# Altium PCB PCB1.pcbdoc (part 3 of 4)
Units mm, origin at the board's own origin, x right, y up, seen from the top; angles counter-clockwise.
Board outline 77.9 x 107.7 mm, 4 copper layers (Top Layer, Inner1, Inner2, Bottom Layer); 106 components, 123 nets, 650 pads, 272 vias.
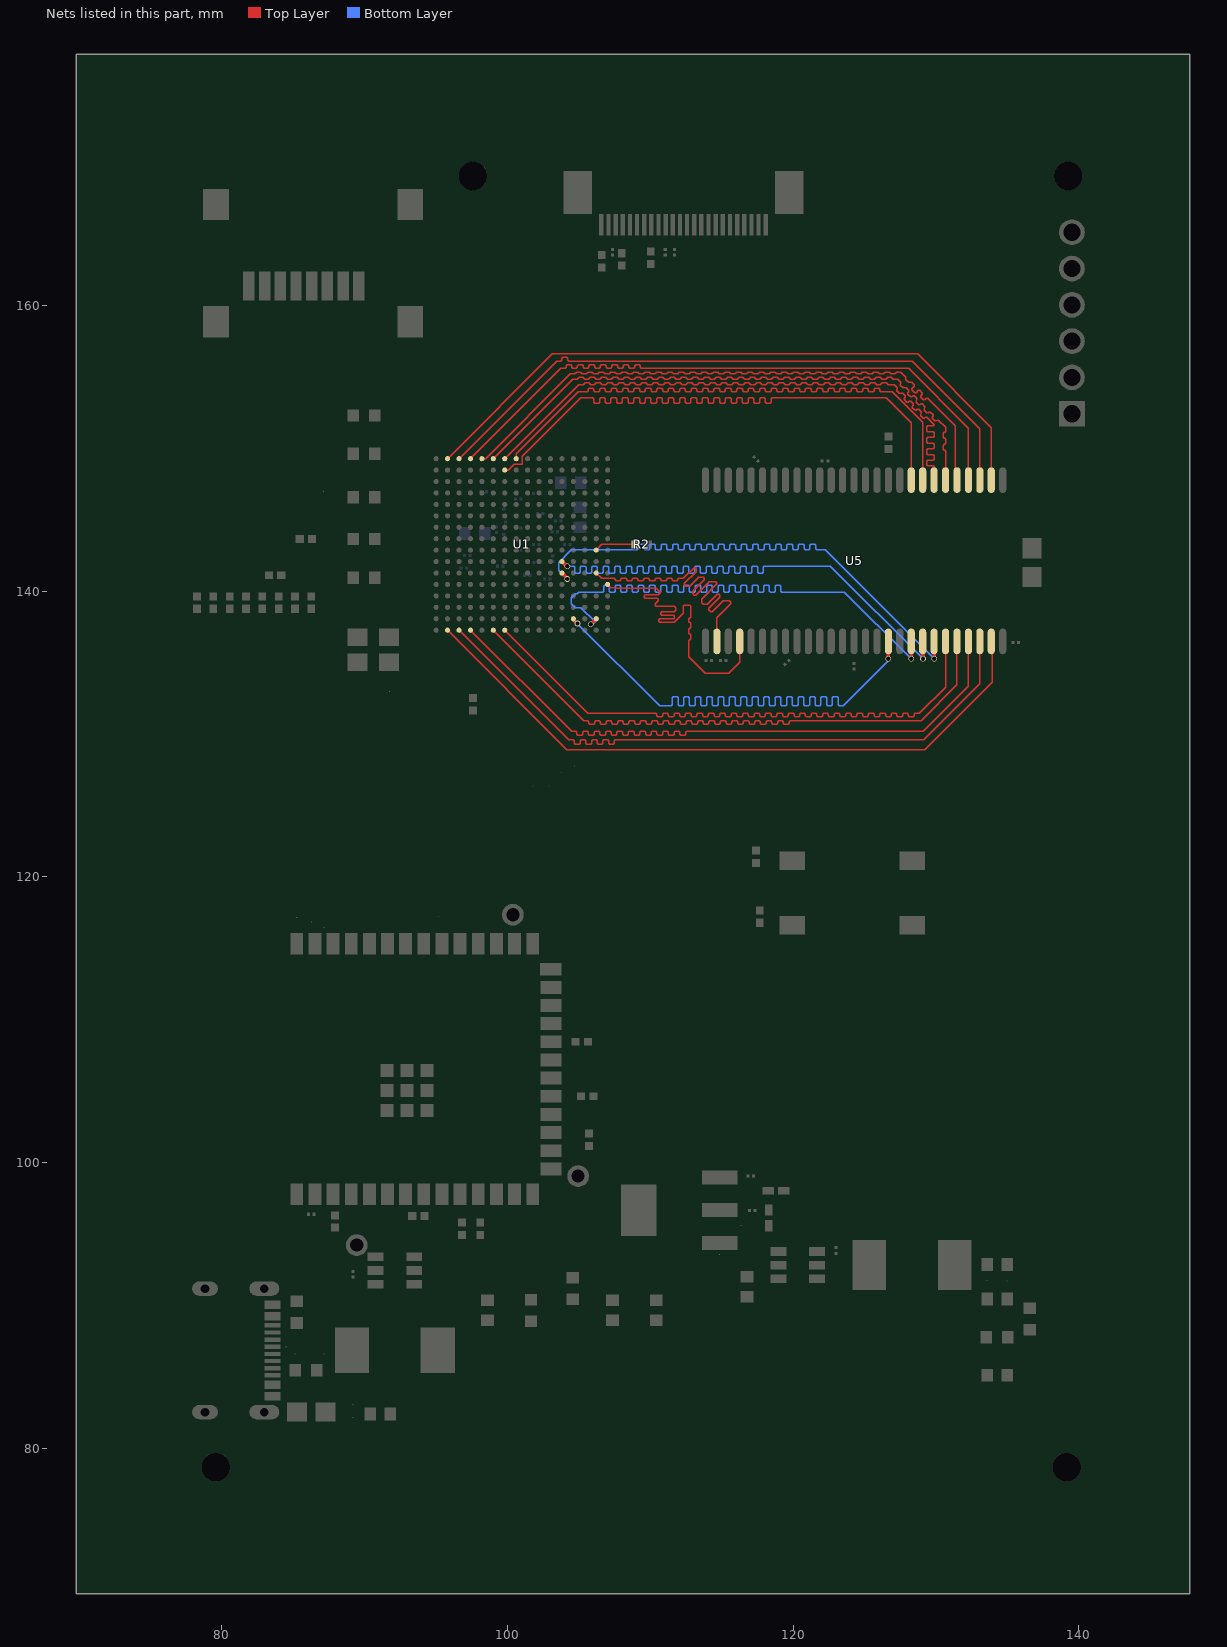
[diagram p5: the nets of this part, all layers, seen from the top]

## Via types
v1: diameter 0.4, hole 0.3, Top Layer to Bottom Layer, 269 vias
v2: diameter 0.5, hole 0.3, Top Layer to Bottom Layer, 3 vias

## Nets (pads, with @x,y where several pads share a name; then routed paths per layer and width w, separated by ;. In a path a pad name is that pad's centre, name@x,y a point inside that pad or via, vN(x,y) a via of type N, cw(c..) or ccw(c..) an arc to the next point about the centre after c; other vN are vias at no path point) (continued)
SD_A0: U1.T6 U5.23 | length 45.3
  Top Layer w0.1: U1.T6@99.024,137.26 105.343,130.941 105.643,130.941 105.714,130.87 105.714,130.758 105.784,130.687 106.043,130.687 106.114,130.758 106.114,130.87 106.184,130.941 106.443,130.941 106.514,130.87 106.514,130.758 106.584,130.687 106.843,130.687 106.914,130.758 106.914,130.87 106.984,130.941 107.243,130.941 107.314,130.87 107.314,130.758 107.384,130.687 107.643,130.687 107.714,130.758 107.714,130.87 107.784,130.941 108.043,130.941 108.114,130.87 108.114,130.758 108.184,130.687 108.443,130.687 108.514,130.758 108.514,130.87 108.584,130.941 108.843,130.941 108.914,130.87 108.914,130.758 108.984,130.687 109.243,130.687 109.314,130.758 109.314,130.87 109.384,130.941 109.643,130.941 109.714,130.87 109.714,130.758 109.784,130.687 110.043,130.687 110.114,130.758 110.114,130.87 110.184,130.941 110.443,130.941 110.514,130.87 110.514,130.758 110.584,130.687 110.843,130.687 110.914,130.758 110.914,130.87 110.984,130.941 111.243,130.941 111.314,130.87 111.314,130.758 111.384,130.687 111.643,130.687 111.714,130.758 111.714,130.87 111.784,130.941 112.043,130.941 112.114,130.87 112.114,130.758 112.184,130.687 112.443,130.687 112.514,130.758 112.514,130.87 112.584,130.941 112.843,130.941 112.914,130.87 112.914,130.758 112.984,130.687 113.243,130.687 113.314,130.758 113.314,130.87 113.384,130.941 113.643,130.941 113.714,130.87 113.714,130.758 113.784,130.687 114.043,130.687 114.114,130.758 114.114,130.87 114.184,130.941 114.443,130.941 114.514,130.87 114.514,130.758 114.584,130.687 114.843,130.687 114.914,130.758 114.914,130.87 114.984,130.941 115.243,130.941 115.314,130.87 115.314,130.758 115.384,130.687 115.643,130.687 115.714,130.758 115.714,130.87 115.784,130.941 116.043,130.941 116.114,130.87 116.114,130.758 116.184,130.687 116.443,130.687 116.514,130.758 116.514,130.87 116.584,130.941 116.843,130.941 116.914,130.87 116.914,130.758 116.984,130.687 117.243,130.687 117.314,130.758 117.314,130.87 117.384,130.941 117.643,130.941 117.714,130.87 117.714,130.758 117.784,130.687 118.043,130.687 118.114,130.758 118.114,130.87 118.184,130.941 118.443,130.941 118.514,130.87 118.514,130.758 118.584,130.687 118.843,130.687 118.914,130.758 118.914,130.87 118.984,130.941 119.243,130.941 119.314,130.87 119.314,130.758 119.384,130.687 119.643,130.687 119.714,130.758 119.714,130.87 119.784,130.941 128.964,130.941 131.465,133.442 U5.23@131.465,136.475
SD_A1: U1.T4 U5.24 | length 45.6
  Top Layer w0.1: U1.T4@97.424,137.26 104.505,130.179 104.805,130.179 104.876,130.108 104.876,129.996 104.946,129.925 105.205,129.925 105.276,129.996 105.276,130.108 105.346,130.179 105.605,130.179 105.676,130.108 105.676,129.996 105.746,129.925 106.005,129.925 106.076,129.996 106.076,130.108 106.146,130.179 106.405,130.179 106.476,130.108 106.476,129.996 106.546,129.925 106.805,129.925 106.876,129.996 106.876,130.108 106.946,130.179 107.205,130.179 107.276,130.108 107.276,129.996 107.346,129.925 107.605,129.925 107.676,129.996 107.676,130.108 107.746,130.179 108.005,130.179 108.076,130.108 108.076,129.996 108.146,129.925 108.405,129.925 108.476,129.996 108.476,130.108 108.546,130.179 108.805,130.179 108.876,130.108 108.876,129.996 108.946,129.925 109.205,129.925 109.276,129.996 109.276,130.108 109.346,130.179 109.605,130.179 109.676,130.108 109.676,129.996 109.746,129.925 110.005,129.925 110.076,129.996 110.076,130.108 110.146,130.179 110.405,130.179 110.476,130.108 110.476,129.996 110.546,129.925 110.805,129.925 110.876,129.996 110.876,130.108 110.946,130.179 111.205,130.179 111.276,130.108 111.276,129.996 111.346,129.925 111.605,129.925 111.676,129.996 111.676,130.108 111.746,130.179 112.005,130.179 112.076,130.108 112.076,129.996 112.146,129.925 112.405,129.925 112.476,129.996 112.476,130.108 112.546,130.179 129.091,130.179 132.266,133.354 U5.24@132.265,136.475
SD_A2: U1.T3 U5.25 | length 45.9
  Top Layer w0.1: U1.T3@96.624,137.26 104.303,129.581 104.626,129.581 104.697,129.51 104.697,129.361 104.767,129.29 105.026,129.29 105.097,129.361 105.097,129.51 105.167,129.581 105.426,129.581 105.497,129.51 105.497,129.361 105.567,129.29 105.826,129.29 105.897,129.361 105.897,129.51 105.967,129.581 106.226,129.581 106.297,129.51 106.297,129.361 106.367,129.29 106.626,129.29 106.697,129.361 106.697,129.51 106.767,129.581 107.026,129.581 107.097,129.51 107.097,129.361 107.167,129.29 107.426,129.29 107.497,129.361 107.497,129.51 107.567,129.581 129.128,129.581 133.065,133.518 U5.25@133.065,136.475
SD_A3: U1.T2 U5.26 | length 46.4
  Top Layer w0.1: U1.T2@95.824,137.26 104.175,128.909 129.218,128.909 133.917,133.608 133.917,136.423 U5.26@133.865,136.475
SD_A4: U1.A2 U5.29 | length 46.9
  Top Layer w0.1: U1.A2@95.824,149.26 103.159,156.595 128.71,156.595 133.865,151.44 U5.29@133.865,147.759
SD_A5: U1.A3 U5.30 | length 45.2
  Top Layer w0.1: U1.A3@96.624,149.26 103.451,156.087 103.751,156.087 103.821,156.158 103.821,156.27 103.892,156.341 104.151,156.341 104.221,156.27 104.221,156.158 104.292,156.087 128.329,156.087 133.065,151.351 U5.30@133.065,147.759
SD_A6: U1.A4 U5.31 | length 45.2
  Top Layer w0.1: U1.A4@97.424,149.26 103.743,155.579 104.043,155.579 104.114,155.65 104.114,155.762 104.184,155.833 104.443,155.833 104.514,155.762 104.514,155.65 104.584,155.579 104.843,155.579 104.914,155.65 104.914,155.762 104.984,155.833 105.243,155.833 105.314,155.762 105.314,155.65 105.384,155.579 105.643,155.579 105.714,155.65 105.714,155.762 105.784,155.833 106.043,155.833 106.114,155.762 106.114,155.65 106.184,155.579 106.443,155.579 106.514,155.65 106.514,155.762 106.584,155.833 106.843,155.833 106.914,155.762 106.914,155.65 106.984,155.579 107.243,155.579 107.314,155.65 107.314,155.762 107.384,155.833 107.643,155.833 107.714,155.762 107.714,155.65 107.784,155.579 108.043,155.579 108.114,155.65 108.114,155.762 108.184,155.833 108.443,155.833 108.514,155.762 108.514,155.65 108.584,155.579 108.843,155.579 108.914,155.65 108.914,155.762 108.984,155.833 109.243,155.833 109.314,155.762 109.314,155.65 109.384,155.579 128.075,155.579 132.265,151.389 U5.31@132.265,147.759
SD_A7: U1.A5 U5.32 | length 45.1
  Top Layer w0.1: U1.A5@98.224,149.26 98.484,149.26 104.422,155.198 104.722,155.198 104.849,155.325 105.122,155.325 105.249,155.198 105.522,155.198 105.649,155.325 105.922,155.325 106.049,155.198 106.322,155.198 106.449,155.325 106.722,155.325 106.849,155.198 107.122,155.198 107.249,155.325 107.522,155.325 107.649,155.198 107.922,155.198 108.049,155.325 108.322,155.325 108.449,155.198 108.722,155.198 108.849,155.325 109.122,155.325 109.249,155.198 109.522,155.198 109.649,155.325 109.922,155.325 110.049,155.198 110.322,155.198 110.449,155.325 110.722,155.325 110.849,155.198 111.122,155.198 111.249,155.325 111.522,155.325 111.649,155.198 111.922,155.198 112.049,155.325 112.322,155.325 112.449,155.198 112.722,155.198 112.849,155.325 113.122,155.325 113.249,155.198 113.522,155.198 113.649,155.325 113.922,155.325 114.049,155.198 114.322,155.198 114.449,155.325 114.722,155.325 114.849,155.198 115.122,155.198 115.249,155.325 115.522,155.325 115.649,155.198 115.922,155.198 116.049,155.325 116.322,155.325 116.449,155.198 116.722,155.198 116.849,155.325 117.122,155.325 117.249,155.198 117.522,155.198 117.649,155.325 117.922,155.325 118.049,155.198 118.322,155.198 118.449,155.325 118.722,155.325 118.849,155.198 119.122,155.198 119.249,155.325 119.522,155.325 119.649,155.198 119.922,155.198 120.049,155.325 120.322,155.325 120.449,155.198 120.722,155.198 120.849,155.325 121.122,155.325 121.249,155.198 121.522,155.198 121.649,155.325 121.922,155.325 122.049,155.198 122.322,155.198 122.449,155.325 122.722,155.325 122.849,155.198 123.122,155.198 123.249,155.325 123.522,155.325 123.649,155.198 123.922,155.198 124.049,155.325 124.322,155.325 124.449,155.198 124.722,155.198 124.849,155.325 125.122,155.325 125.249,155.198 125.522,155.198 125.649,155.325 125.922,155.325 126.049,155.198 126.322,155.198 126.449,155.325 126.722,155.325 126.849,155.198 127.122,155.198 127.249,155.325 127.522,155.325 127.894,154.953 127.894,154.774 128.077,154.591 128.177,154.591 128.189,154.603 128.289,154.603 128.472,154.42 128.472,154.32 128.317,154.166 128.317,154.066 128.5,153.883 128.6,153.883 128.754,154.037 128.854,154.037 129.037,153.854 129.037,153.754 128.932,153.649 128.932,153.549 129.114,153.366 129.214,153.366 129.32,153.472 129.42,153.472 131.338,151.554 131.338,147.886 U5.32@131.465,147.759
SD_A8: U1.A6 U5.33 | length 44.4
  Top Layer w0.1: U1.A6@99.024,149.26 104.581,154.817 104.881,154.817 104.952,154.888 104.952,154.898 105.022,154.969 105.281,154.969 105.352,154.898 105.352,154.888 105.422,154.817 105.681,154.817 105.752,154.888 105.752,154.898 105.822,154.969 106.081,154.969 106.152,154.898 106.152,154.888 106.222,154.817 106.481,154.817 106.552,154.888 106.552,154.898 106.622,154.969 106.881,154.969 106.952,154.898 106.952,154.888 107.022,154.817 107.281,154.817 107.352,154.888 107.352,154.898 107.422,154.969 107.681,154.969 107.752,154.898 107.752,154.888 107.822,154.817 108.081,154.817 108.152,154.888 108.152,154.898 108.222,154.969 108.481,154.969 108.552,154.898 108.552,154.888 108.622,154.817 108.881,154.817 108.952,154.888 108.952,154.898 109.022,154.969 109.281,154.969 109.352,154.898 109.352,154.888 109.422,154.817 109.681,154.817 109.752,154.888 109.752,154.898 109.822,154.969 110.081,154.969 110.152,154.898 110.152,154.888 110.222,154.817 110.481,154.817 110.552,154.888 110.552,154.898 110.622,154.969 110.881,154.969 110.952,154.898 110.952,154.888 111.022,154.817 111.281,154.817 111.352,154.888 111.352,154.898 111.422,154.969 111.681,154.969 111.752,154.898 111.752,154.888 111.822,154.817 112.081,154.817 112.152,154.888 112.152,154.898 112.222,154.969 112.481,154.969 112.552,154.898 112.552,154.888 112.622,154.817 112.881,154.817 112.952,154.888 112.952,154.898 113.022,154.969 113.281,154.969 113.352,154.898 113.352,154.888 113.422,154.817 113.681,154.817 113.752,154.888 113.752,154.898 113.822,154.969 114.081,154.969 114.152,154.898 114.152,154.888 114.222,154.817 114.481,154.817 114.552,154.888 114.552,154.898 114.622,154.969 114.881,154.969 114.952,154.898 114.952,154.888 115.022,154.817 115.281,154.817 115.352,154.888 115.352,154.898 115.422,154.969 115.681,154.969 115.752,154.898 115.752,154.888 115.822,154.817 116.081,154.817 116.152,154.888 116.152,154.898 116.222,154.969 116.481,154.969 116.552,154.898 116.552,154.888 116.622,154.817 116.881,154.817 116.952,154.888 116.952,154.898 117.022,154.969 117.281,154.969 117.352,154.898 117.352,154.888 117.422,154.817 117.681,154.817 117.752,154.888 117.752,154.898 117.822,154.969 118.081,154.969 118.152,154.898 118.152,154.888 118.222,154.817 118.481,154.817 118.552,154.888 118.552,154.898 118.622,154.969 118.881,154.969 118.952,154.898 118.952,154.888 119.022,154.817 119.281,154.817 119.352,154.888 119.352,154.898 119.422,154.969 119.681,154.969 119.752,154.898 119.752,154.888 119.822,154.817 120.081,154.817 120.152,154.888 120.152,154.898 120.222,154.969 120.481,154.969 120.552,154.898 120.552,154.888 120.622,154.817 120.881,154.817 120.952,154.888 120.952,154.898 121.022,154.969 121.281,154.969 121.352,154.898 121.352,154.888 121.422,154.817 121.681,154.817 121.752,154.888 121.752,154.898 121.822,154.969 122.081,154.969 122.152,154.898 122.152,154.888 122.222,154.817 122.481,154.817 122.552,154.888 122.552,154.898 122.622,154.969 122.881,154.969 122.952,154.898 122.952,154.888 123.022,154.817 123.281,154.817 123.352,154.888 123.352,154.898 123.422,154.969 123.681,154.969 123.752,154.898 123.752,154.888 123.822,154.817 124.081,154.817 124.152,154.888 124.152,154.898 124.222,154.969 124.481,154.969 124.552,154.898 124.552,154.888 124.622,154.817 124.881,154.817 124.952,154.888 124.952,154.898 125.022,154.969 125.281,154.969 125.352,154.898 125.352,154.888 125.422,154.817 125.681,154.817 125.752,154.888 125.752,154.898 125.822,154.969 126.081,154.969 126.152,154.898 126.152,154.888 126.222,154.817 126.481,154.817 126.552,154.888 126.552,154.898 126.622,154.969 126.881,154.969 126.952,154.898 126.952,154.888 127.022,154.817 127.313,154.817 127.525,154.605 127.525,154.505 127.513,154.493 127.513,154.393 127.696,154.21 127.796,154.21 127.808,154.222 127.908,154.222 128.091,154.039 128.091,153.939 128.035,153.884 128.035,153.784 128.218,153.601 128.318,153.601 128.373,153.656 128.473,153.656 128.656,153.473 128.656,153.373 128.601,153.318 128.601,153.218 128.784,153.035 128.884,153.035 128.939,153.091 129.039,153.091 129.222,152.908 129.222,152.808 129.167,152.752 129.167,152.652 129.349,152.47 129.449,152.47 129.505,152.525 129.605,152.525 129.788,152.342 129.788,152.242 129.741,152.196 129.741,152.096 129.924,151.913 130.024,151.913 130.071,151.959 130.171,151.959 130.665,151.465 130.665,151.165 130.594,151.094 130.577,151.094 130.506,151.024 130.506,150.765 130.577,150.694 130.594,150.694 130.665,150.624 130.665,150.324 130.594,150.253 130.577,150.253 130.506,150.182 130.506,149.924 130.577,149.853 130.594,149.853 130.665,149.782 U5.33@130.665,147.759
SD_A9: U1.A7 U5.34 | length 45.4
  Top Layer w0.1: U1.A7@99.824,149.26 105,154.436 105.3,154.436 105.371,154.507 105.371,154.517 105.441,154.588 105.7,154.588 105.771,154.517 105.771,154.507 105.841,154.436 106.1,154.436 106.171,154.507 106.171,154.517 106.241,154.588 106.5,154.588 106.571,154.517 106.571,154.507 106.641,154.436 106.9,154.436 106.971,154.507 106.971,154.517 107.041,154.588 107.3,154.588 107.371,154.517 107.371,154.507 107.441,154.436 107.7,154.436 107.771,154.507 107.771,154.517 107.841,154.588 108.1,154.588 108.171,154.517 108.171,154.507 108.241,154.436 108.5,154.436 108.571,154.507 108.571,154.517 108.641,154.588 108.9,154.588 108.971,154.517 108.971,154.507 109.041,154.436 109.3,154.436 109.371,154.507 109.371,154.517 109.441,154.588 109.7,154.588 109.771,154.517 109.771,154.507 109.841,154.436 110.1,154.436 110.171,154.507 110.171,154.517 110.241,154.588 110.5,154.588 110.571,154.517 110.571,154.507 110.641,154.436 110.9,154.436 110.971,154.507 110.971,154.517 111.041,154.588 111.3,154.588 111.371,154.517 111.371,154.507 111.441,154.436 111.7,154.436 111.771,154.507 111.771,154.517 111.841,154.588 112.1,154.588 112.171,154.517 112.171,154.507 112.241,154.436 112.5,154.436 112.571,154.507 112.571,154.517 112.641,154.588 112.9,154.588 112.971,154.517 112.971,154.507 113.041,154.436 113.3,154.436 113.371,154.507 113.371,154.517 113.441,154.588 113.7,154.588 113.771,154.517 113.771,154.507 113.841,154.436 114.1,154.436 114.171,154.507 114.171,154.517 114.241,154.588 114.5,154.588 114.571,154.517 114.571,154.507 114.641,154.436 114.9,154.436 114.971,154.507 114.971,154.517 115.041,154.588 115.3,154.588 115.371,154.517 115.371,154.507 115.441,154.436 115.7,154.436 115.771,154.507 115.771,154.517 115.841,154.588 116.1,154.588 116.171,154.517 116.171,154.507 116.241,154.436 116.5,154.436 116.571,154.507 116.571,154.517 116.641,154.588 116.9,154.588 116.971,154.517 116.971,154.507 117.041,154.436 117.3,154.436 117.371,154.507 117.371,154.517 117.441,154.588 117.7,154.588 117.771,154.517 117.771,154.507 117.841,154.436 118.1,154.436 118.171,154.507 118.171,154.517 118.241,154.588 118.5,154.588 118.571,154.517 118.571,154.507 118.641,154.436 118.9,154.436 118.971,154.507 118.971,154.517 119.041,154.588 119.3,154.588 119.371,154.517 119.371,154.507 119.441,154.436 119.7,154.436 119.771,154.507 119.771,154.517 119.841,154.588 120.1,154.588 120.171,154.517 120.171,154.507 120.241,154.436 120.5,154.436 120.571,154.507 120.571,154.517 120.641,154.588 120.9,154.588 120.971,154.517 120.971,154.507 121.041,154.436 121.3,154.436 121.371,154.507 121.371,154.517 121.441,154.588 121.7,154.588 121.771,154.517 121.771,154.507 121.841,154.436 122.1,154.436 122.171,154.507 122.171,154.517 122.241,154.588 122.5,154.588 122.571,154.517 122.571,154.507 122.641,154.436 122.9,154.436 122.971,154.507 122.971,154.517 123.041,154.588 123.3,154.588 123.371,154.517 123.371,154.507 123.441,154.436 123.7,154.436 123.771,154.507 123.771,154.517 123.841,154.588 124.1,154.588 124.171,154.517 124.171,154.507 124.241,154.436 124.5,154.436 124.571,154.507 124.571,154.517 124.641,154.588 124.9,154.588 124.971,154.517 124.971,154.507 125.041,154.436 125.3,154.436 125.371,154.507 125.371,154.517 125.441,154.588 125.7,154.588 125.771,154.517 125.771,154.507 125.841,154.436 126.1,154.436 126.171,154.507 126.171,154.517 126.241,154.588 126.5,154.588 126.571,154.517 126.571,154.507 126.641,154.436 127.059,154.436 127.271,154.224 127.271,154.124 127.259,154.112 127.259,154.012 127.442,153.829 127.542,153.829 127.554,153.841 127.654,153.841 127.837,153.658 127.837,153.558 127.781,153.503 127.781,153.403 127.964,153.22 128.064,153.22 128.119,153.275 128.219,153.275 128.402,153.092 128.402,152.992 128.347,152.937 128.347,152.837 128.53,152.654 128.63,152.654 128.685,152.71 128.785,152.71 128.968,152.527 128.968,152.427 128.913,152.371 128.913,152.271 129.095,152.089 129.195,152.089 129.251,152.144 129.351,152.144 129.865,151.63 129.865,151.622 129.794,151.551 129.416,151.551 129.345,151.481 129.345,151.222 129.416,151.151 129.794,151.151 129.865,151.081 129.865,150.822 129.794,150.751 129.416,150.751 129.345,150.681 129.345,150.422 129.416,150.351 129.794,150.351 129.865,150.281 129.865,150.022 129.794,149.951 129.416,149.951 129.345,149.881 129.345,149.622 129.416,149.551 129.794,149.551 129.865,149.481 129.865,149.222 129.794,149.151 129.416,149.151 129.345,149.081 129.345,148.822 129.416,148.751 129.794,148.751 129.865,148.681 U5.34@129.865,147.759
SD_A10: U1.T7 U5.22 | length 45.1
  Top Layer w0.1: U1.T7@99.824,137.26 105.635,131.449 110.395,131.449 110.466,131.378 110.466,131.266 110.537,131.195 110.795,131.195 110.866,131.266 110.866,131.378 110.937,131.449 111.195,131.449 111.266,131.378 111.266,131.266 111.337,131.195 111.595,131.195 111.666,131.266 111.666,131.378 111.737,131.449 111.995,131.449 112.066,131.378 112.066,131.266 112.137,131.195 112.395,131.195 112.466,131.266 112.466,131.378 112.537,131.449 112.795,131.449 112.866,131.378 112.866,131.266 112.937,131.195 113.195,131.195 113.266,131.266 113.266,131.378 113.337,131.449 113.595,131.449 113.666,131.378 113.666,131.266 113.737,131.195 113.995,131.195 114.066,131.266 114.066,131.378 114.137,131.449 114.395,131.449 114.466,131.378 114.466,131.266 114.537,131.195 114.795,131.195 114.866,131.266 114.866,131.378 114.937,131.449 115.195,131.449 115.266,131.378 115.266,131.266 115.337,131.195 115.595,131.195 115.666,131.266 115.666,131.378 115.737,131.449 115.995,131.449 116.066,131.378 116.066,131.266 116.137,131.195 116.395,131.195 116.466,131.266 116.466,131.378 116.537,131.449 116.795,131.449 116.866,131.378 116.866,131.266 116.937,131.195 117.195,131.195 117.266,131.266 117.266,131.378 117.337,131.449 117.595,131.449 117.666,131.378 117.666,131.266 117.737,131.195 117.995,131.195 118.066,131.266 118.066,131.378 118.137,131.449 118.395,131.449 118.466,131.378 118.466,131.266 118.537,131.195 118.795,131.195 118.866,131.266 118.866,131.378 118.937,131.449 119.195,131.449 119.266,131.378 119.266,131.266 119.337,131.195 119.595,131.195 119.666,131.266 119.666,131.378 119.737,131.449 119.995,131.449 120.066,131.378 120.066,131.266 120.137,131.195 120.395,131.195 120.466,131.266 120.466,131.378 120.537,131.449 120.795,131.449 120.866,131.378 120.866,131.266 120.937,131.195 121.195,131.195 121.266,131.266 121.266,131.378 121.337,131.449 121.595,131.449 121.666,131.378 121.666,131.266 121.737,131.195 121.995,131.195 122.066,131.266 122.066,131.378 122.137,131.449 122.395,131.449 122.466,131.378 122.466,131.266 122.537,131.195 122.795,131.195 122.866,131.266 122.866,131.378 122.937,131.449 123.195,131.449 123.266,131.378 123.266,131.266 123.337,131.195 123.595,131.195 123.666,131.266 123.666,131.378 123.737,131.449 123.995,131.449 124.066,131.378 124.066,131.266 124.137,131.195 124.395,131.195 124.466,131.266 124.466,131.378 124.537,131.449 124.795,131.449 124.866,131.378 124.866,131.266 124.937,131.195 125.195,131.195 125.266,131.266 125.266,131.378 125.337,131.449 125.595,131.449 125.666,131.378 125.666,131.266 125.737,131.195 125.995,131.195 126.066,131.266 126.066,131.378 126.137,131.449 126.395,131.449 126.466,131.378 126.466,131.266 126.537,131.195 126.795,131.195 126.866,131.266 126.866,131.378 126.937,131.449 127.195,131.449 127.266,131.378 127.266,131.266 127.337,131.195 127.595,131.195 127.666,131.266 127.666,131.378 127.737,131.449 127.995,131.449 128.066,131.378 128.066,131.266 128.137,131.195 128.395,131.195 128.466,131.266 128.466,131.378 128.537,131.449 128.837,131.449 130.665,133.277 U5.22@130.665,136.475
SD_A11: U1.A8 U5.35 | length 44.4
  Top Layer w0.1: U1.A8@100.624,149.26 100.624,149.591 104.961,153.928 105.592,153.928 105.662,153.999 105.662,154.111 105.733,154.182 105.992,154.182 106.062,154.111 106.062,153.999 106.133,153.928 106.392,153.928 106.462,153.999 106.462,154.111 106.533,154.182 106.792,154.182 106.862,154.111 106.862,153.999 106.933,153.928 107.192,153.928 107.262,153.999 107.262,154.111 107.333,154.182 107.592,154.182 107.662,154.111 107.662,153.999 107.733,153.928 107.992,153.928 108.062,153.999 108.062,154.111 108.133,154.182 108.392,154.182 108.462,154.111 108.462,153.999 108.533,153.928 108.792,153.928 108.862,153.999 108.862,154.111 108.933,154.182 109.192,154.182 109.262,154.111 109.262,153.999 109.333,153.928 109.592,153.928 109.662,153.999 109.662,154.111 109.733,154.182 109.992,154.182 110.062,154.111 110.062,153.999 110.133,153.928 110.392,153.928 110.462,153.999 110.462,154.111 110.533,154.182 110.792,154.182 110.862,154.111 110.862,153.999 110.933,153.928 111.192,153.928 111.262,153.999 111.262,154.111 111.333,154.182 111.592,154.182 111.662,154.111 111.662,153.999 111.733,153.928 111.992,153.928 112.062,153.999 112.062,154.111 112.133,154.182 112.392,154.182 112.462,154.111 112.462,153.999 112.533,153.928 112.792,153.928 112.862,153.999 112.862,154.111 112.933,154.182 113.192,154.182 113.262,154.111 113.262,153.999 113.333,153.928 113.592,153.928 113.662,153.999 113.662,154.111 113.733,154.182 113.992,154.182 114.062,154.111 114.062,153.999 114.133,153.928 114.392,153.928 114.462,153.999 114.462,154.111 114.533,154.182 114.792,154.182 114.862,154.111 114.862,153.999 114.933,153.928 115.192,153.928 115.262,153.999 115.262,154.111 115.333,154.182 115.592,154.182 115.662,154.111 115.662,153.999 115.733,153.928 115.992,153.928 116.062,153.999 116.062,154.111 116.133,154.182 116.392,154.182 116.462,154.111 116.462,153.999 116.533,153.928 116.792,153.928 116.862,153.999 116.862,154.111 116.933,154.182 117.192,154.182 117.262,154.111 117.262,153.999 117.333,153.928 117.592,153.928 117.662,153.999 117.662,154.111 117.733,154.182 117.992,154.182 118.062,154.111 118.062,153.999 118.133,153.928 118.392,153.928 118.462,153.999 118.462,154.111 118.533,154.182 118.792,154.182 118.862,154.111 118.862,153.999 118.933,153.928 119.192,153.928 119.262,153.999 119.262,154.111 119.333,154.182 119.592,154.182 119.662,154.111 119.662,153.999 119.733,153.928 119.992,153.928 120.062,153.999 120.062,154.111 120.133,154.182 120.392,154.182 120.462,154.111 120.462,153.999 120.533,153.928 120.792,153.928 120.862,153.999 120.862,154.111 120.933,154.182 121.192,154.182 121.262,154.111 121.262,153.999 121.333,153.928 121.592,153.928 121.662,153.999 121.662,154.111 121.733,154.182 121.992,154.182 122.062,154.111 122.062,153.999 122.133,153.928 122.392,153.928 122.462,153.999 122.462,154.111 122.533,154.182 122.792,154.182 122.862,154.111 122.862,153.999 122.933,153.928 123.192,153.928 123.262,153.999 123.262,154.111 123.333,154.182 123.592,154.182 123.662,154.111 123.662,153.999 123.733,153.928 123.992,153.928 124.062,153.999 124.062,154.111 124.133,154.182 124.392,154.182 124.462,154.111 124.462,153.999 124.533,153.928 124.792,153.928 124.862,153.999 124.862,154.111 124.933,154.182 125.192,154.182 125.262,154.111 125.262,153.999 125.333,153.928 125.592,153.928 125.662,153.999 125.662,154.111 125.733,154.182 125.992,154.182 126.062,154.111 126.062,153.999 126.133,153.928 126.932,153.928 129.065,151.795 U5.35@129.065,147.759
SD_A12: U1.B7 U5.36 | length 45.1
  Top Layer w0.1: U1.B7@99.824,148.46 100.084,148.46 100.502,148.878 101.016,148.878 101.042,148.903 101.042,149.418 105.144,153.52 105.984,153.52 106.055,153.449 106.055,153.21 106.125,153.139 106.384,153.139 106.455,153.21 106.455,153.449 106.525,153.52 106.784,153.52 106.855,153.449 106.855,153.21 106.925,153.139 107.184,153.139 107.255,153.21 107.255,153.449 107.325,153.52 107.584,153.52 107.655,153.449 107.655,153.21 107.725,153.139 107.984,153.139 108.055,153.21 108.055,153.449 108.125,153.52 108.384,153.52 108.455,153.449 108.455,153.21 108.525,153.139 108.784,153.139 108.855,153.21 108.855,153.449 108.925,153.52 109.184,153.52 109.255,153.449 109.255,153.21 109.325,153.139 109.584,153.139 109.655,153.21 109.655,153.449 109.725,153.52 109.984,153.52 110.055,153.449 110.055,153.21 110.125,153.139 110.384,153.139 110.455,153.21 110.455,153.449 110.525,153.52 110.784,153.52 110.855,153.449 110.855,153.21 110.925,153.139 111.184,153.139 111.255,153.21 111.255,153.449 111.325,153.52 111.584,153.52 111.655,153.449 111.655,153.21 111.725,153.139 111.984,153.139 112.055,153.21 112.055,153.449 112.125,153.52 112.384,153.52 112.455,153.449 112.455,153.21 112.525,153.139 112.784,153.139 112.855,153.21 112.855,153.449 112.925,153.52 113.184,153.52 113.255,153.449 113.255,153.21 113.325,153.139 113.584,153.139 113.655,153.21 113.655,153.449 113.725,153.52 113.984,153.52 114.055,153.449 114.055,153.21 114.125,153.139 114.384,153.139 114.455,153.21 114.455,153.449 114.525,153.52 114.784,153.52 114.855,153.449 114.855,153.21 114.925,153.139 115.184,153.139 115.255,153.21 115.255,153.449 115.325,153.52 115.584,153.52 115.655,153.449 115.655,153.21 115.725,153.139 115.984,153.139 116.055,153.21 116.055,153.449 116.125,153.52 116.384,153.52 116.455,153.449 116.455,153.21 116.525,153.139 116.784,153.139 116.855,153.21 116.855,153.449 116.925,153.52 117.184,153.52 117.255,153.449 117.255,153.21 117.325,153.139 117.584,153.139 117.655,153.21 117.655,153.449 117.725,153.52 117.984,153.52 118.055,153.449 118.055,153.21 118.125,153.139 118.384,153.139 118.455,153.21 118.455,153.449 118.525,153.52 126.524,153.52 128.265,151.779 U5.36@128.265,147.759
SD_BA0: U1.K12 U5.20 | length 43.4
  Top Layer w0.254: U1.K12@103.824,142.06 104.15,141.734 v1(104.197,141.734) ; U5.20@129.065,136.475 129.091,136.449 v1(129.091,135.259)
  Bottom Layer w0.1: v1(104.197,141.734) 104.638,141.734 104.709,141.664 104.709,141.308 104.78,141.237 105.038,141.237 105.109,141.308 105.109,141.664 105.18,141.734 105.438,141.734 105.509,141.664 105.509,141.308 105.58,141.237 105.838,141.237 105.909,141.308 105.909,141.664 105.98,141.734 106.238,141.734 106.309,141.664 106.309,141.308 106.38,141.237 106.638,141.237 106.709,141.308 106.709,141.664 106.78,141.734 107.038,141.734 107.109,141.664 107.109,141.308 107.18,141.237 107.438,141.237 107.509,141.308 107.509,141.664 107.58,141.734 107.838,141.734 107.909,141.664 107.909,141.308 107.98,141.237 108.238,141.237 108.309,141.308 108.309,141.664 108.38,141.734 108.638,141.734 108.709,141.664 108.709,141.308 108.78,141.237 109.038,141.237 109.109,141.308 109.109,141.664 109.18,141.734 109.438,141.734 109.509,141.664 109.509,141.308 109.58,141.237 109.838,141.237 109.909,141.308 109.909,141.664 109.98,141.734 110.238,141.734 110.309,141.664 110.309,141.308 110.38,141.237 110.638,141.237 110.709,141.308 110.709,141.664 110.78,141.734 111.038,141.734 111.109,141.664 111.109,141.308 111.18,141.237 111.438,141.237 111.509,141.308 111.509,141.664 111.58,141.734 111.838,141.734 111.909,141.664 111.909,141.308 111.98,141.237 112.238,141.237 112.309,141.308 112.309,141.664 112.38,141.734 112.638,141.734 112.709,141.664 112.709,141.308 112.78,141.237 113.038,141.237 113.109,141.308 113.109,141.664 113.18,141.734 113.438,141.734 113.509,141.664 113.509,141.308 113.58,141.237 113.838,141.237 113.909,141.308 113.909,141.664 113.98,141.734 114.238,141.734 114.309,141.664 114.309,141.308 114.38,141.237 114.638,141.237 114.709,141.308 114.709,141.664 114.78,141.734 115.038,141.734 115.109,141.664 115.109,141.308 115.18,141.237 115.438,141.237 115.509,141.308 115.509,141.664 115.58,141.734 115.838,141.734 115.909,141.664 115.909,141.308 115.98,141.237 116.238,141.237 116.309,141.308 116.309,141.664 116.38,141.734 116.638,141.734 116.709,141.664 116.709,141.308 116.78,141.237 117.038,141.237 117.109,141.308 117.109,141.664 117.18,141.734 117.438,141.734 117.509,141.664 117.509,141.308 117.58,141.237 117.838,141.237 117.909,141.308 117.909,141.664 117.98,141.734 122.615,141.734 v1(129.091,135.259)
SD_BA1: U1.L12 U5.21 | length 42.5
  Top Layer w0.254: U1.L12@103.824,141.26 104.199,140.885 v1(104.199,140.847) ; v1(129.865,135.259) U5.21@129.865,136.475
  Bottom Layer w0.1: v1(104.199,140.847) 103.595,141.451 103.595,141.984 104.49,142.879 109.098,142.879 109.169,142.95 109.169,143.189 109.24,143.26 109.498,143.26 109.569,143.189 109.569,142.95 109.64,142.879 109.898,142.879 109.969,142.95 109.969,143.189 110.04,143.26 110.298,143.26 110.369,143.189 110.369,142.95 110.44,142.879 110.698,142.879 110.769,142.95 110.769,143.189 110.84,143.26 111.098,143.26 111.169,143.189 111.169,142.95 111.24,142.879 111.498,142.879 111.569,142.95 111.569,143.189 111.64,143.26 111.898,143.26 111.969,143.189 111.969,142.95 112.04,142.879 112.298,142.879 112.369,142.95 112.369,143.189 112.44,143.26 112.698,143.26 112.769,143.189 112.769,142.95 112.84,142.879 113.098,142.879 113.169,142.95 113.169,143.189 113.24,143.26 113.498,143.26 113.569,143.189 113.569,142.95 113.64,142.879 113.898,142.879 113.969,142.95 113.969,143.189 114.04,143.26 114.298,143.26 114.369,143.189 114.369,142.95 114.44,142.879 114.698,142.879 114.769,142.95 114.769,143.189 114.84,143.26 115.098,143.26 115.169,143.189 115.169,142.95 115.24,142.879 115.498,142.879 115.569,142.95 115.569,143.189 115.64,143.26 115.898,143.26 115.969,143.189 115.969,142.95 116.04,142.879 116.298,142.879 116.369,142.95 116.369,143.189 116.44,143.26 116.698,143.26 116.769,143.189 116.769,142.95 116.84,142.879 117.098,142.879 117.169,142.95 117.169,143.189 117.24,143.26 117.498,143.26 117.569,143.189 117.569,142.95 117.64,142.879 117.898,142.879 117.969,142.95 117.969,143.189 118.04,143.26 118.298,143.26 118.369,143.189 118.369,142.95 118.44,142.879 118.698,142.879 118.769,142.95 118.769,143.189 118.84,143.26 119.098,143.26 119.169,143.189 119.169,142.95 119.24,142.879 119.498,142.879 119.569,142.95 119.569,143.189 119.64,143.26 119.898,143.26 119.969,143.189 119.969,142.95 120.04,142.879 120.298,142.879 120.369,142.95 120.369,143.189 120.44,143.26 120.698,143.26 120.769,143.189 120.769,142.95 120.84,142.879 121.098,142.879 121.169,142.95 121.169,143.189 121.24,143.26 121.498,143.26 121.569,143.189 121.569,142.95 121.64,142.879 122.245,142.879 v1(129.865,135.259)
SD_CAS_N: U1.R13 U5.17 | length 43.1
  Top Layer w0.254: U1.R13@104.624,138.06 104.624,138.012 v1(104.912,137.724) ; v1(126.665,135.259) U5.17@126.665,136.475
  Bottom Layer w0.1: v1(104.912,137.724) 110.656,131.98 111.476,131.98 111.546,132.051 111.546,132.521 111.617,132.592 111.876,132.592 111.946,132.521 111.946,132.051 112.017,131.98 112.276,131.98 112.346,132.051 112.346,132.521 112.417,132.592 112.676,132.592 112.746,132.521 112.746,132.051 112.817,131.98 113.076,131.98 113.146,132.051 113.146,132.521 113.217,132.592 113.476,132.592 113.546,132.521 113.546,132.051 113.617,131.98 113.876,131.98 113.946,132.051 113.946,132.521 114.017,132.592 114.276,132.592 114.346,132.521 114.346,132.051 114.417,131.98 114.676,131.98 114.746,132.051 114.746,132.521 114.817,132.592 115.076,132.592 115.146,132.521 115.146,132.051 115.217,131.98 115.476,131.98 115.546,132.051 115.546,132.521 115.617,132.592 115.876,132.592 115.946,132.521 115.946,132.051 116.017,131.98 116.276,131.98 116.346,132.051 116.346,132.521 116.417,132.592 116.676,132.592 116.746,132.521 116.746,132.051 116.817,131.98 117.076,131.98 117.146,132.051 117.146,132.521 117.217,132.592 117.476,132.592 117.546,132.521 117.546,132.051 117.617,131.98 117.876,131.98 117.946,132.051 117.946,132.521 118.017,132.592 118.276,132.592 118.346,132.521 118.346,132.051 118.417,131.98 118.676,131.98 118.746,132.051 118.746,132.521 118.817,132.592 119.076,132.592 119.146,132.521 119.146,132.051 119.217,131.98 119.476,131.98 119.546,132.051 119.546,132.521 119.617,132.592 119.876,132.592 119.946,132.521 119.946,132.051 120.017,131.98 120.276,131.98 120.346,132.051 120.346,132.521 120.417,132.592 120.676,132.592 120.746,132.521 120.746,132.051 120.817,131.98 121.076,131.98 121.146,132.051 121.146,132.521 121.217,132.592 121.476,132.592 121.546,132.521 121.546,132.051 121.617,131.98 121.876,131.98 121.946,132.051 121.946,132.521 122.017,132.592 122.276,132.592 122.346,132.521 122.346,132.051 122.417,131.98 122.676,131.98 122.746,132.051 122.746,132.521 122.817,132.592 123.076,132.592 123.146,132.521 123.146,132.051 123.217,131.98 123.517,131.98 126.665,135.128 v1(126.665,135.259)
SD_CLK: R2.2 U1.J15 | length 2.9
  Top Layer w0.1: U1.J15@106.224,142.86 106.624,143.26 R2.2@108.973,143.26
SD_CS_N: U1.R15 U5.19 | length 43
  Top Layer w0.254: v1(105.85,137.672) 106.224,138.046 U1.R15@106.224,138.06 ; v1(128.265,135.259) U5.19@128.265,136.475
  Bottom Layer w0.1: v1(105.85,137.672) 105.977,137.672 106.146,137.841 105.143,138.844 104.762,138.844 104.482,139.125 104.482,139.521 104.762,139.802 104.889,139.802 105.016,139.929 106.677,139.929 106.747,140 106.747,140.329 106.818,140.4 107.077,140.4 107.147,140.329 107.147,140 107.218,139.929 107.477,139.929 107.547,140 107.547,140.329 107.618,140.4 107.877,140.4 107.947,140.329 107.947,140 108.018,139.929 108.277,139.929 108.347,140 108.347,140.329 108.418,140.4 108.677,140.4 108.747,140.329 108.747,140 108.818,139.929 109.077,139.929 109.147,140 109.147,140.329 109.218,140.4 109.477,140.4 109.547,140.329 109.547,140 109.618,139.929 109.877,139.929 109.947,140 109.947,140.329 110.018,140.4 110.277,140.4 110.347,140.329 110.347,140 110.418,139.929 110.677,139.929 110.747,140 110.747,140.329 110.818,140.4 111.077,140.4 111.147,140.329 111.147,140 111.218,139.929 111.477,139.929 111.547,140 111.547,140.329 111.618,140.4 111.877,140.4 111.947,140.329 111.947,140 112.018,139.929 112.277,139.929 112.347,140 112.347,140.329 112.418,140.4 112.677,140.4 112.747,140.329 112.747,140 112.818,139.929 113.077,139.929 113.147,140 113.147,140.329 113.218,140.4 113.477,140.4 113.547,140.329 113.547,140 113.618,139.929 113.877,139.929 113.947,140 113.947,140.329 114.018,140.4 114.277,140.4 114.347,140.329 114.347,140 114.418,139.929 114.677,139.929 114.747,140 114.747,140.329 114.818,140.4 115.077,140.4 115.147,140.329 115.147,140 115.218,139.929 115.477,139.929 115.547,140 115.547,140.329 115.618,140.4 115.877,140.4 115.947,140.329 115.947,140 116.018,139.929 116.277,139.929 116.347,140 116.347,140.329 116.418,140.4 116.677,140.4 116.747,140.329 116.747,140 116.818,139.929 117.077,139.929 117.147,140 117.147,140.329 117.218,140.4 117.477,140.4 117.547,140.329 117.547,140 117.618,139.929 117.877,139.929 117.947,140 117.947,140.329 118.018,140.4 118.277,140.4 118.347,140.329 118.347,140 118.418,139.929 118.677,139.929 118.747,140 118.747,140.329 118.818,140.4 119.077,140.4 119.147,140.329 119.147,140 119.218,139.929 123.574,139.929 128.117,135.386 128.138,135.386 v1(128.265,135.259)
SD_DQ0: U1.L15 U5.2 | length 25
  Top Layer w0.1: U1.L15@106.224,141.26 106.606,140.878 107.473,140.878 107.543,140.807 107.543,140.791 107.614,140.72 107.873,140.72 107.943,140.791 107.943,140.807 108.014,140.878 108.273,140.878 108.343,140.807 108.343,140.791 108.414,140.72 108.673,140.72 108.743,140.791 108.743,140.807 108.814,140.878 109.073,140.878 109.143,140.807 109.143,140.791 109.214,140.72 109.473,140.72 109.543,140.791 109.543,140.807 109.614,140.878 109.873,140.878 109.943,140.807 109.943,140.791 110.014,140.72 110.273,140.72 110.343,140.791 110.343,140.807 110.414,140.878 110.673,140.878 110.743,140.807 110.743,140.791 110.814,140.72 111.073,140.72 111.143,140.791 111.143,140.807 111.214,140.878 111.473,140.878 111.543,140.807 111.543,140.791 111.614,140.72 111.873,140.72 111.943,140.791 111.943,140.807 112.014,140.878 112.314,140.878 113.074,141.638 113.187,141.638 113.216,141.609 113.216,141.355 112.393,140.532 112.393,140.4 112.454,140.339 112.755,140.339 113.39,140.974 113.699,140.974 113.77,140.903 113.77,140.803 112.962,139.995 112.962,139.831 113.089,139.704 113.179,139.704 114.139,140.664 114.594,140.664 114.665,140.593 114.665,140.499 113.597,139.431 113.597,139.196 113.724,139.069 113.978,139.069 114.684,139.775 114.796,139.775 114.867,139.704 114.867,139.552 114.105,138.79 114.105,138.688 114.232,138.561 114.359,138.561 115.121,139.323 115.519,139.323 115.639,139.202 115.639,139.102 114.665,138.128 U5.2@114.665,136.602
SD_DQ1: U1.M16 U5.4 | length 25
  Top Layer w0.1: U1.M16@107.024,140.46 107.24,140.244 107.5,140.244 107.539,140.206 110.428,140.206 110.729,139.905 110.558,139.733 109.66,139.733 109.589,139.662 109.589,139.562 109.66,139.492 110.507,139.492 110.549,139.45 110.549,139.311 110.351,139.114 110.351,139.014 110.422,138.943 111.691,138.943 111.798,138.836 111.798,138.667 111.671,138.54 110.803,138.54 110.738,138.475 110.738,138.383 110.803,138.319 111.691,138.319 111.691,138.085 111.674,138.067 110.676,138.067 110.605,137.997 110.605,137.897 110.676,137.826 111.691,137.826 112.327,138.462 112.327,138.942 112.398,139.013 112.764,139.013 112.835,138.942 112.835,138.18 112.708,138.053 112.708,137.849 112.828,137.729 112.828,137.449 112.708,137.329 112.708,137.049 112.828,136.929 112.828,136.649 112.708,136.529 112.708,135.386 113.851,134.243 115.502,134.243 116.265,135.006 U5.4@116.265,136.602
